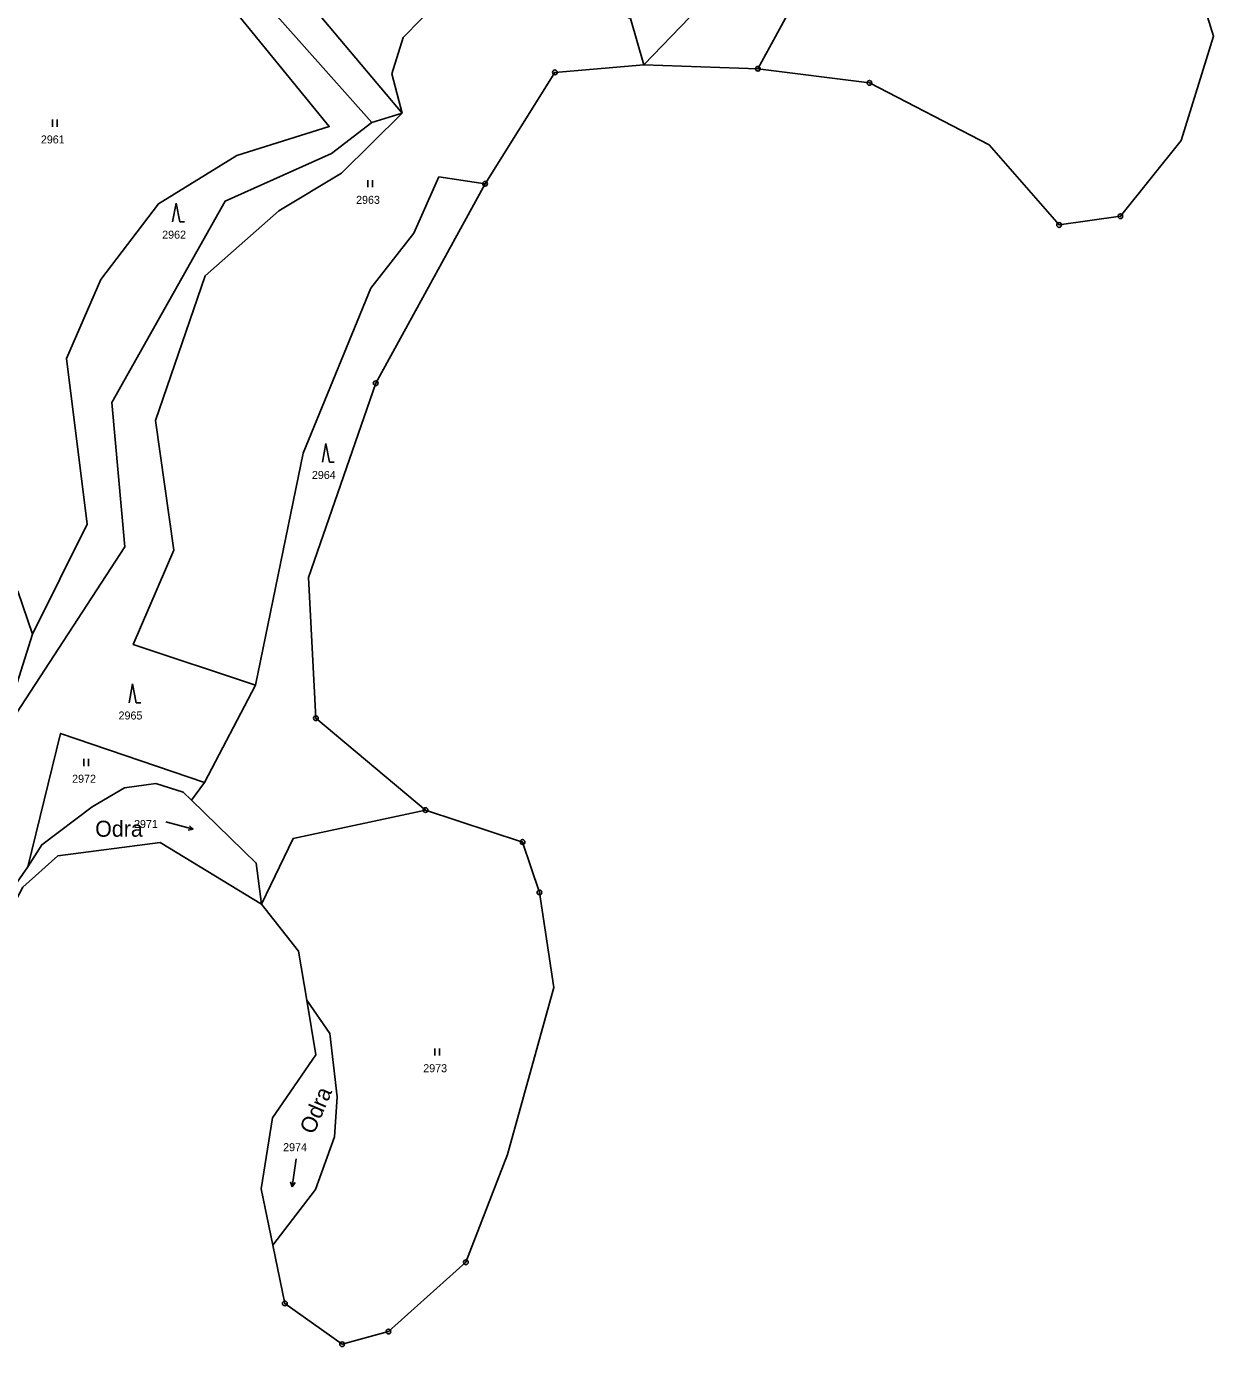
# Model space of a CAD drawing. Extents: x -504988 to -494607, y -1123820 to -1114018.
# Drawn here: x -496759.4 to -496507.4, y -1121858.7 to -1121578.3 of the extents above; entities that cross this region are included whole.
import ezdxf

# ---------------------------------------------------------------- set-up
doc = ezdxf.new("R2010")
doc.units = 0
for name, color, linetype in [('Hranice parcel', 7, 'Continuous'), ('Parcelní čísla', 7, 'Continuous'), ('Pop  PČ popisy', 7, 'Continuous'), ('Značky bodu BP', 7, 'Continuous'), ('Značky kultur', 7, 'Continuous')]:
    doc.layers.add(name, color=color, linetype=linetype)

msp = doc.modelspace()

# ---------------------------------------------------------------- linework, layer by layer
at = {"layer": 'Hranice parcel'}
for p, q in [((-496732.53, -1121533.92), (-496679.69, -1121596.75)), ((-496590.79, -1121562.78), (-496604.12, -1121587.34)), ((-496628.32, -1121586.51), (-496604.12, -1121587.34)), ((-496679.69, -1121596.75), (-496686.13, -1121598.72)), ((-496710.82, -1121718.26), (-496721.64, -1121738.9)), ((-496721.64, -1121738.9), (-496724.42, -1121742.69))]:
    msp.add_line(p, q, dxfattribs=at)
for points in [[(-496628.32, -1121586.51), (-496602.98, -1121560.16), (-496591.11, -1121531.58)], [(-496514.28, -1121602.59), (-496507.37, -1121580.43), (-496514.02, -1121558.9), (-496512.9, -1121532.93)], [(-496686.13, -1121598.72), (-496714.85, -1121566.43), (-496732.5, -1121541.44)], [(-496758.17, -1121707.39), (-496746.55, -1121684.08), (-496750.96, -1121648.86), (-496743.63, -1121632.12), (-496731.41, -1121616.02), (-496714.73, -1121605.77), (-496695.15, -1121599.6), (-496717.82, -1121571.78), (-496733.06, -1121546.75), (-496743.91, -1121546.74), (-496755.6, -1121552.41)], [(-496755.6, -1121552.41), (-496755.84, -1121556.71), (-496786.34, -1121602.24), (-496790.93, -1121617.84), (-496789.5, -1121631.19), (-496787.93, -1121654.85), (-496788.06, -1121674.86), (-496781.27, -1121683.85), (-496768.89, -1121690.38), (-496761.24, -1121698.29), (-496758.17, -1121707.39)], [(-496628.32, -1121586.51), (-496631.2, -1121576.69), (-496648.43, -1121569.4), (-496668.19, -1121569.15), (-496679.47, -1121580.69), (-496681.86, -1121588.4), (-496679.69, -1121596.75)], [(-496662.05, -1121611.76), (-496647.24, -1121588.1), (-496628.32, -1121586.51)], [(-496604.12, -1121587.34), (-496580.46, -1121590.33), (-496555.03, -1121603.53)], [(-496679.69, -1121596.75), (-496692.51, -1121609.49), (-496705.81, -1121617.51), (-496721.51, -1121631.33), (-496732.01, -1121662.01), (-496728.16, -1121689.59), (-496736.74, -1121709.58), (-496710.82, -1121718.26)], [(-496765.2, -1121722.65), (-496761.54, -1121724.18), (-496738.55, -1121688.86), (-496741.27, -1121658.22), (-496717.26, -1121615.45), (-496694.65, -1121605.37), (-496686.13, -1121598.72)], [(-496555.03, -1121603.53), (-496540.16, -1121620.52), (-496527.15, -1121618.67), (-496514.28, -1121602.59)], [(-496710.82, -1121718.26), (-496700.7, -1121668.97), (-496686.34, -1121633.95), (-496677.18, -1121622.26), (-496671.87, -1121610.3), (-496662.05, -1121611.76)], [(-496674.68, -1121744.78), (-496697.98, -1121725.26), (-496699.51, -1121695.36), (-496685.28, -1121654.13), (-496662.05, -1121611.76)], [(-496758.17, -1121707.39), (-496761.37, -1121717.72), (-496765.2, -1121722.65)], [(-496759.15, -1121756.8), (-496752.18, -1121728.51), (-496721.64, -1121738.9)], [(-496724.42, -1121742.69), (-496726.19, -1121740.99), (-496731.94, -1121739.15), (-496738.61, -1121740.05), (-496745.5, -1121744.07), (-496756.14, -1121752.14), (-496759.15, -1121756.8)], [(-496724.42, -1121742.69), (-496710.63, -1121756.05), (-496709.51, -1121764.78)], [(-496709.51, -1121764.78), (-496702.81, -1121750.8), (-496674.68, -1121744.78)], [(-496647.46, -1121782.45), (-496650.5, -1121762.27), (-496654.08, -1121751.56), (-496674.68, -1121744.78)], [(-496752.79, -1121754.51), (-496731.01, -1121751.69), (-496709.51, -1121764.78)], [(-496763.89, -1121768.09), (-496760.23, -1121761.17), (-496752.79, -1121754.51)], [(-496766.24, -1121768.1), (-496765.38, -1121765.71), (-496759.15, -1121756.8)], [(-496709.51, -1121764.78), (-496701.64, -1121774.76), (-496699.9, -1121785.16)], [(-496682.57, -1121855.52), (-496666.11, -1121840.8), (-496657.3, -1121817.91), (-496647.46, -1121782.45)], [(-496699.9, -1121785.16), (-496697.96, -1121796.76), (-496707.2, -1121810.14)], [(-496699.9, -1121785.16), (-496695.02, -1121792.2), (-496693.44, -1121805.7), (-496694.05, -1121814.18), (-496698.07, -1121825.34), (-496707.12, -1121837.16)], [(-496707.2, -1121810.14), (-496709.58, -1121825.25), (-496707.12, -1121837.16)], [(-496707.12, -1121837.16), (-496704.57, -1121849.55), (-496692.41, -1121858.22), (-496682.57, -1121855.52)]]:
    msp.add_lwpolyline(points, dxfattribs=at)
at = {"layer": 'Značky bodu BP'}
for centre, radius in [((-496647.24, -1121588.1), 0.5), ((-496647.24, -1121588.1), 0.0303), ((-496604.12, -1121587.34), 0.5), ((-496604.12, -1121587.34), 0.0303), ((-496580.46, -1121590.33), 0.5), ((-496580.46, -1121590.33), 0.0303), ((-496662.05, -1121611.76), 0.5), ((-496662.05, -1121611.76), 0.0303), ((-496540.16, -1121620.52), 0.5), ((-496527.15, -1121618.67), 0.5), ((-496527.15, -1121618.67), 0.0303), ((-496540.16, -1121620.52), 0.0303), ((-496685.28, -1121654.13), 0.5), ((-496685.28, -1121654.13), 0.0303), ((-496697.98, -1121725.26), 0.5), ((-496697.98, -1121725.26), 0.0303), ((-496674.68, -1121744.78), 0.5), ((-496674.68, -1121744.78), 0.0303), ((-496654.08, -1121751.56), 0.5), ((-496654.08, -1121751.56), 0.0303), ((-496650.5, -1121762.27), 0.5), ((-496650.5, -1121762.27), 0.0303), ((-496666.11, -1121840.8), 0.5), ((-496666.11, -1121840.8), 0.0303), ((-496704.57, -1121849.55), 0.5), ((-496704.57, -1121849.55), 0.0303), ((-496682.57, -1121855.52), 0.5), ((-496682.57, -1121855.52), 0.0303), ((-496692.41, -1121858.22), 0.5), ((-496692.41, -1121858.22), 0.0303)]:
    msp.add_circle(centre, radius, dxfattribs=at)
at = {"layer": 'Značky kultur'}
for p, q in [((-496753.91, -1121599.65), (-496753.91, -1121598.15)), ((-496752.91, -1121599.65), (-496752.91, -1121598.15)), ((-496686.98, -1121612.48), (-496686.98, -1121610.98)), ((-496685.98, -1121612.48), (-496685.98, -1121610.98)), ((-496727.64, -1121615.88), (-496728.39, -1121619.88)), ((-496726.89, -1121619.88), (-496727.64, -1121615.88)), ((-496726.89, -1121619.88), (-496725.89, -1121619.88)), ((-496695.85, -1121666.91), (-496696.6, -1121670.91)), ((-496695.1, -1121670.91), (-496695.85, -1121666.91)), ((-496695.1, -1121670.91), (-496694.1, -1121670.91)), ((-496736.9, -1121717.99), (-496737.65, -1121721.99)), ((-496736.15, -1121721.99), (-496736.9, -1121717.99)), ((-496736.15, -1121721.99), (-496735.15, -1121721.99)), ((-496747.27, -1121735.42), (-496747.27, -1121733.92)), ((-496746.27, -1121735.42), (-496746.27, -1121733.92)), ((-496729.81, -1121747.29), (-496724.02, -1121748.84)), ((-496724.02, -1121748.84), (-496725.09, -1121749.07)), ((-496724.02, -1121748.84), (-496724.83, -1121748.1)), ((-496672.72, -1121796.9), (-496672.72, -1121795.4)), ((-496671.72, -1121796.9), (-496671.72, -1121795.4)), ((-496702.15, -1121818.82), (-496702.99, -1121824.77)), ((-496702.99, -1121824.77), (-496703.35, -1121823.73)), ((-496702.99, -1121824.77), (-496702.36, -1121823.87))]:
    msp.add_line(p, q, dxfattribs=at)

# ---------------------------------------------------------------- texts
at = {"layer": 'Parcelní čísla'}
for s, p in [('2961', (-496756.37, -1121603.2)), ('2963', (-496689.44, -1121616.03)), ('2962', (-496730.61, -1121623.43)), ('2964', (-496698.82, -1121674.46)), ('2965', (-496739.87, -1121725.54)), ('2972', (-496749.73, -1121738.97)), ('2971', (-496736.59, -1121748.59)), ('2973', (-496675.18, -1121800.45)), ('2974', (-496704.93, -1121817.22))]:
    msp.add_text(s, height=1.7, dxfattribs=at).set_placement(p)
at = {"layer": 'Pop  PČ popisy'}
msp.add_text('Odra', height=3.4, dxfattribs=at).set_placement((-496744.84, -1121750.44))
msp.add_text('Odra', height=3.4, rotation=67, dxfattribs=at).set_placement((-496698.42, -1121813.82))

doc.saveas('drawing.dxf')
